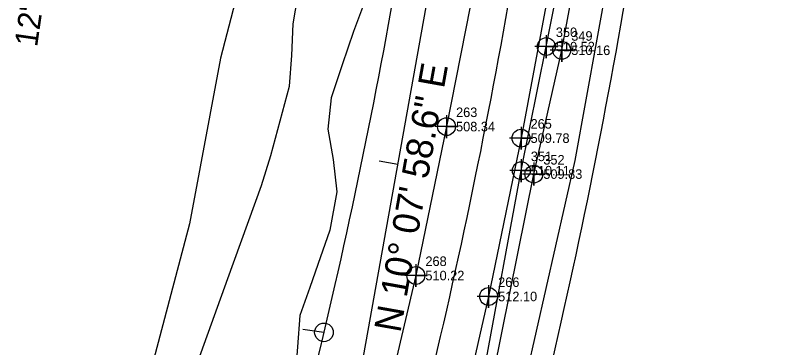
# Model space of a CAD drawing. Extents: x 1698744 to 1699848, y 707609 to 709748.
# Drawn here: x 1699252.7 to 1699456.2, y 708532.2 to 708619.2 of the extents above; entities that cross this region are included whole.
import ezdxf

# ---------------------------------------------------------------- set-up
doc = ezdxf.new("R2010")
doc.units = 0
for name, color, linetype in [('Exist Horizontal Alignment', 7, 'Continuous'), ('Exist Horizontal Baseline Alignment', 7, 'Continuous'), ('Exist Horizontal Baseline Alignment Direction Label', 7, 'Continuous'), ('Exist Horizontal Baseline Alignment Tick small', 7, 'Continuous'), ('Exist Horizontal T-Line Alignment Station Label', 7, 'Continuous'), ('Exist Right of Way Line', 7, 'Continuous'), ('Exist Utilities Power Pole CELL', 7, 'Continuous'), ('Exist Utilities Telephone UG Cable', 7, 'Continuous'), ('Exist Vegetation Woods Line', 7, 'Continuous'), ('Prop North Arrow NAD83 for Plan Sheets CELL', 7, 'Continuous'), ('Prop Roadway Bridge', 7, 'Continuous'), ('Prop Superelevation Label', 7, 'Continuous'), ('Sheet Border Standard 30in CELL', 7, 'Continuous'), ('Sheet Data Field CELL', 7, 'Continuous'), ('Sheet Plot Border Inside CELL', 7, 'Continuous'), ('Sheet Sticker Preliminary CELL', 7, 'Continuous')]:
    doc.layers.add(name, color=color, linetype=linetype)

# ---------------------------------------------------------------- blocks, each defined once
blk = doc.blocks.new('EXIST UTILITIES POWER POLE')
at = {"layer": 'Exist Utilities Power Pole CELL'}
for q in [(0, 0.1125), (0, 0)]:
    blk.add_line((0, 0), q, dxfattribs=at)
blk.add_circle((0, 0), 0.049, dxfattribs=at)

msp = doc.modelspace()

# ---------------------------------------------------------------- linework, layer by layer
at = {"layer": 'Exist Horizontal Alignment'}
msp.add_arc((1697769.66, 708905.56), 1637.02, 343.81554, 351.76048, dxfattribs=at)
at = {"layer": 'Exist Horizontal Baseline Alignment'}
msp.add_line((1699300.22, 708284.8), (1699395.77, 708819.44), dxfattribs=at)
at = {"layer": 'Exist Horizontal Baseline Alignment Tick small'}
msp.add_line((1699353, 708580.12), (1699348.07, 708581), dxfattribs=at)
at = {"layer": 'Exist Right of Way Line'}
for radius in [1607.02, 1667.02]:
    msp.add_arc((1697769.66, 708905.56), radius, 343.81554, 351.76048, dxfattribs=at)
at = {"layer": 'Exist Utilities Telephone UG Cable'}
for points in [[(1699289.3, 708261.63), (1699294.43, 708273.12), (1699294.98, 708276.83), (1699297.07, 708285.75), (1699311.34, 708314.93), (1699319.1, 708332.56), (1699334.97, 708376.04), (1699350.59, 708425.33), (1699363.42, 708472.58), (1699375.64, 708525.91), (1699385.35, 708578.54), (1699391.92, 708611.09), (1699402.91, 708666.14), (1699411.8, 708684.88), (1699423.83, 708686.96)], [(1699289.84, 708261.32), (1699295.04, 708272.93), (1699298.75, 708275.67), (1699309.11, 708275.76), (1699298.02, 708276.51), (1699308.57, 708296.28), (1699314.92, 708313.46), (1699314.86, 708313.64), (1699322.03, 708331.11), (1699337.42, 708375.35), (1699353.54, 708424.71), (1699366.13, 708472.26), (1699378.19, 708525.57), (1699388.64, 708577.64), (1699395.96, 708610.12), (1699406.09, 708665.12), (1699412.51, 708682.93), (1699423.83, 708686.97)]]:
    msp.add_lwpolyline(points, dxfattribs=at)
at = {"layer": 'Exist Vegetation Woods Line'}
for points in [[(1699376.64, 708480.5), (1699399.52, 708581.24), (1699411.03, 708644.91), (1699418.07, 708678.94), (1699422.78, 708694.33), (1699426.7, 708705.17), (1699429.48, 708713.14), (1699432, 708720.11), (1699434.28, 708726.42), (1699436.53, 708730.61), (1699439.28, 708730.63), (1699443.79, 708728.73), (1699446.7, 708722.85), (1699447.62, 708713.57), (1699449.18, 708705.72), (1699451.78, 708697.92), (1699455.63, 708691.45), (1699462.74, 708687.53)], [(1699319.63, 708582.56), (1699324.55, 708600.69), (1699325.14, 708608.79), (1699325.53, 708617.07), (1699326.74, 708624.3), (1699335.04, 708654.62), (1699341.19, 708681.05), (1699343.56, 708702.93), (1699343.9, 708713.27), (1699342.92, 708717.58), (1699340.2, 708718.69), (1699337.21, 708717.02), (1699334.74, 708712.63), (1699324.59, 708674.3), (1699314.16, 708637.68), (1699306.5, 708608.06), (1699298.33, 708564.62), (1699288.14, 708525.9)], [(1699344.47, 708623.53), (1699341.39, 708615.01), (1699338.34, 708606.29), (1699335.53, 708597.67), (1699334.58, 708589.43), (1699336.02, 708581.48), (1699336.98, 708573), (1699335.14, 708562.97), (1699332.03, 708553.9), (1699329.87, 708547.92), (1699327.27, 708540.52), (1699326.67, 708532.29), (1699326.04, 708524.43)], [(1699294.37, 708511.46), (1699308.39, 708550.24), (1699317.2, 708574.63), (1699319.63, 708582.56)]]:
    msp.add_lwpolyline(points, dxfattribs=at)
at = {"layer": 'Prop North Arrow NAD83 for Plan Sheets CELL'}
for points in [[(1699391.92, 708614.09), (1699391.92, 708608.09), (1699391.92, 708611.09), (1699394.92, 708611.09), (1699388.92, 708611.09)], [(1699395.96, 708613.12), (1699395.96, 708607.12), (1699395.96, 708610.12), (1699398.96, 708610.12), (1699392.96, 708610.12)], [(1699385.35, 708581.54), (1699385.35, 708575.54), (1699385.35, 708578.54), (1699388.35, 708578.54), (1699382.35, 708578.54)], [(1699388.64, 708580.64), (1699388.64, 708574.64), (1699388.64, 708577.64), (1699391.64, 708577.64), (1699385.64, 708577.64)]]:
    msp.add_lwpolyline(points, dxfattribs=at)
for centre in [(1699391.92, 708611.09), (1699395.96, 708610.12), (1699385.35, 708578.54), (1699388.64, 708577.64)]:
    msp.add_circle(centre, 2.34, dxfattribs=at)
at = {"layer": 'Sheet Border Standard 30in CELL'}
for points in [[(1699365.75, 708593.1), (1699365.75, 708587.1), (1699365.75, 708590.1), (1699368.75, 708590.1), (1699362.75, 708590.1)], [(1699385.29, 708590.07), (1699385.29, 708584.07), (1699385.29, 708587.07), (1699388.29, 708587.07), (1699382.29, 708587.07)], [(1699357.71, 708554.03), (1699357.71, 708548.03), (1699357.71, 708551.03), (1699360.71, 708551.03), (1699354.71, 708551.03)], [(1699376.79, 708548.54), (1699376.79, 708542.54), (1699376.79, 708545.54), (1699379.79, 708545.54), (1699373.79, 708545.54)]]:
    msp.add_lwpolyline(points, dxfattribs=at)
for centre in [(1699365.75, 708590.1), (1699385.29, 708587.07), (1699357.71, 708551.03), (1699376.79, 708545.54)]:
    msp.add_circle(centre, 2.34, dxfattribs=at)
at = {"layer": 'Sheet Sticker Preliminary CELL'}
for points in [[(1699383.99, 708713.52), (1699382.64, 708696.23), (1699380.52, 708673.61), (1699373.15, 708627.94), (1699365.75, 708590.1), (1699357.71, 708551.03), (1699349.2, 708514.92), (1699339.66, 708477.57), (1699327.77, 708437.19), (1699316.49, 708399.68), (1699302.08, 708358.62), (1699291.44, 708329.76), (1699274.25, 708290.35), (1699255.98, 708255.28)], [(1699407.41, 708710.01), (1699406.15, 708702.08), (1699403.21, 708691.12), (1699399.8, 708670.63), (1699392.32, 708624.59), (1699385.29, 708587.07), (1699376.79, 708545.54), (1699368.8, 708510.47), (1699358.65, 708471.57), (1699347.31, 708431.93), (1699335.28, 708393.42), (1699320.77, 708351.4), (1699309.77, 708322.46), (1699291.82, 708282.07), (1699273.74, 708246.39)]]:
    msp.add_lwpolyline(points, dxfattribs=at)

# ---------------------------------------------------------------- block references
at = {"layer": 'Exist Utilities Power Pole CELL', "xscale": 50.00000000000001, "yscale": 49.99999999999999, "rotation": 82.38044720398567}
msp.add_blockref('EXIST UTILITIES POWER POLE', (1699333.6, 708536.13), dxfattribs=at)

# ---------------------------------------------------------------- texts
at = {"layer": 'Exist Horizontal Baseline Alignment Direction Label'}
msp.add_text('N 10%%d 07\' 58.6" E', height=7, rotation=79.8671, dxfattribs=at).set_placement((1699353.62, 708535.84))
at = {"layer": 'Exist Horizontal T-Line Alignment Station Label'}
msp.add_text('12" SPIKE SET', height=6, rotation=81.8739, dxfattribs=at).set_placement((1699258.36, 708610.83))
at = {"layer": 'Prop Roadway Bridge'}
for s, p in [('510.52', (1699394.42, 708609.84)), ('510.16', (1699398.46, 708608.87)), ('510.11', (1699387.85, 708577.29)), ('509.83', (1699391.14, 708576.39))]:
    msp.add_text(s, height=2.5, dxfattribs=at).set_placement(p)
at = {"layer": 'Prop Superelevation Label'}
for s, p in [('350', (1699394.42, 708613.59)), ('349', (1699398.46, 708612.62)), ('351', (1699387.85, 708581.04)), ('352', (1699391.14, 708580.14))]:
    msp.add_text(s, height=2.5, dxfattribs=at).set_placement(p)
at = {"layer": 'Sheet Data Field CELL'}
for s, p in [('263', (1699368.25, 708592.6)), ('265', (1699387.79, 708589.57)), ('268', (1699360.21, 708553.53)), ('266', (1699379.29, 708548.04))]:
    msp.add_text(s, height=2.5, dxfattribs=at).set_placement(p)
at = {"layer": 'Sheet Plot Border Inside CELL'}
for s, p in [('508.34', (1699368.25, 708588.85)), ('509.78', (1699387.79, 708585.82)), ('510.22', (1699360.21, 708549.78)), ('512.10', (1699379.29, 708544.29))]:
    msp.add_text(s, height=2.5, dxfattribs=at).set_placement(p)

doc.saveas('drawing.dxf')
